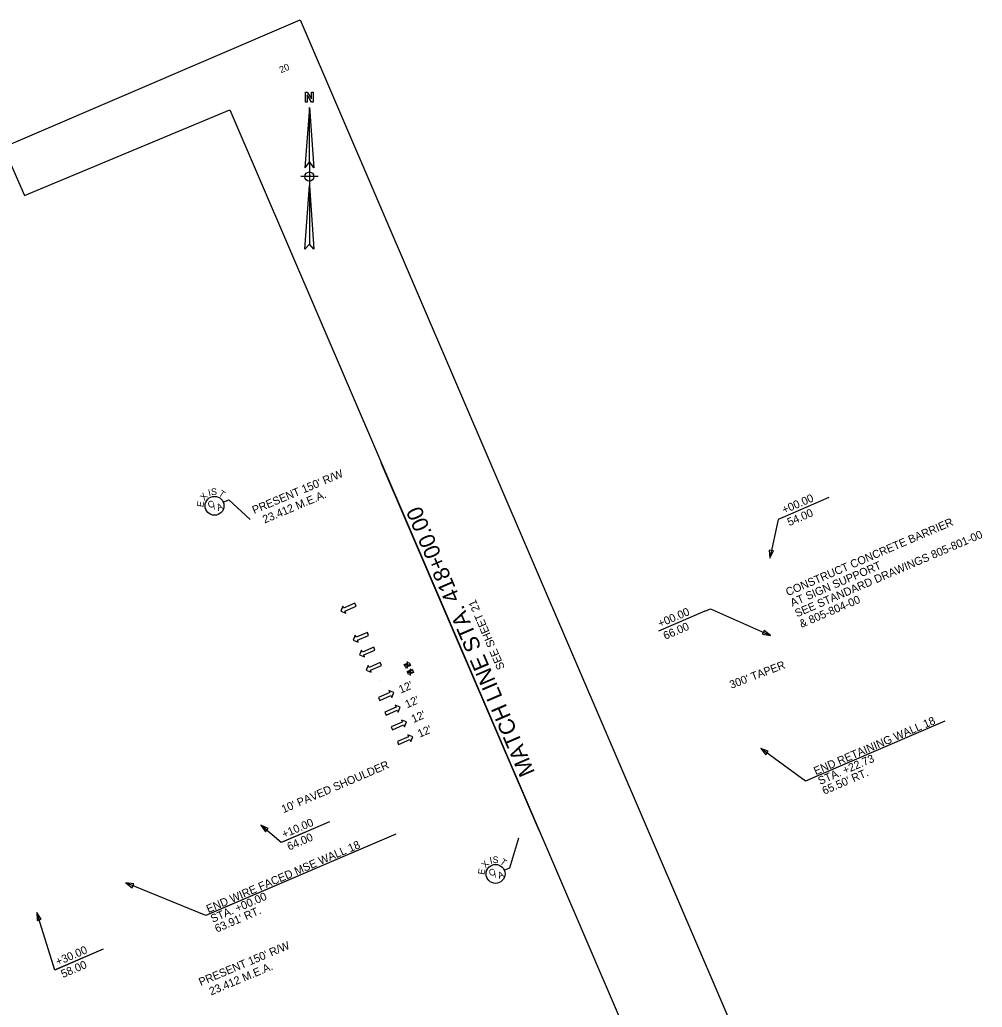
# Model space of a CAD drawing. Extents: x 1618233 to 1620283, y 1101130 to 1102832.
# Drawn here: x 1619562 to 1620283, y 1101953 to 1102693 of the extents above; entities that cross this region are included whole.
import ezdxf

# ---------------------------------------------------------------- set-up
doc = ezdxf.new("R2010")
doc.units = 0
for name, color, linetype in [('RD_EX_BldgApp', 7, 'Continuous'), ('RD_EX_Driveway', 7, 'Continuous'), ('RD_EX_Fence_Other', 7, 'Continuous'), ('RD_EX_H2O_WetLd', 7, 'Continuous'), ('RD_EX_Misc', 7, 'Continuous'), ('RD_EX_Misc_Golf_Teebox', 7, 'Continuous'), ('RD_EX_RailRoad', 7, 'Continuous'), ('RD_EX_UT', 7, 'Continuous'), ('RD_EX_VEG', 7, 'Continuous'), ('RD_HC_Data', 7, 'Continuous')]:
    doc.layers.add(name, color=color, linetype=linetype)

msp = doc.modelspace()

# ---------------------------------------------------------------- linework, layer by layer
at = {"layer": 'RD_EX_Driveway'}
for points in [[(1619854.18, 1102211.71), (1619855.07, 1102209.64), (1619851.38, 1102208.06), (1619850.49, 1102210.14), (1619854.18, 1102211.71)], [(1619855.28, 1102209.07), (1619855.15, 1102209.4), (1619851.45, 1102207.83), (1619851.58, 1102207.52)], [(1619856.34, 1102206.65), (1619856.4, 1102206.51), (1619852.83, 1102204.94), (1619852.76, 1102205.13)], [(1619856.54, 1102206.28), (1619857.42, 1102204.21), (1619853.73, 1102202.64), (1619852.85, 1102204.71), (1619856.54, 1102206.28)]]:
    msp.add_lwpolyline(points, dxfattribs=at)
at = {"layer": 'RD_EX_Fence_Other'}
msp.add_lwpolyline([(1618233.15, 1102032.67), (1619772.37, 1102693.29), (1620149.61, 1101814.32), (1618610.39, 1101153.71)], close=True, dxfattribs=at)
at = {"layer": 'RD_EX_H2O_WetLd'}
for p, q in [((1619852.82, 1102207.38), (1619852.82, 1102212.38)), ((1619850.32, 1102209.88), (1619855.32, 1102209.88)), ((1619852.63, 1102204.4), (1619857.63, 1102204.4)), ((1619855.13, 1102201.9), (1619855.13, 1102206.9))]:
    msp.add_line(p, q, dxfattribs=at)
at = {"layer": 'RD_EX_Misc'}
for points in [[(1619814.4, 1102253.86), (1619813.45, 1102256.07), (1619805.02, 1102252.45), (1619804.38, 1102253.94), (1619802.9, 1102250.23), (1619806.61, 1102248.75), (1619805.97, 1102250.24)], [(1619823.77, 1102232.01), (1619822.82, 1102234.22), (1619814.4, 1102230.6), (1619813.75, 1102232.1), (1619812.27, 1102228.38), (1619815.99, 1102226.9), (1619815.34, 1102228.4)], [(1619828.52, 1102220.96), (1619827.57, 1102223.16), (1619819.14, 1102219.54), (1619818.5, 1102221.04), (1619817.02, 1102217.33), (1619820.73, 1102215.84), (1619820.09, 1102217.34)], [(1619833.45, 1102209.45), (1619832.51, 1102211.66), (1619824.08, 1102208.04), (1619823.44, 1102209.54), (1619821.95, 1102205.82), (1619825.67, 1102204.34), (1619825.03, 1102205.84)], [(1619831.1, 1102185.52), (1619832.04, 1102183.32), (1619840.47, 1102186.94), (1619841.11, 1102185.44), (1619842.6, 1102189.15), (1619838.88, 1102190.64), (1619839.52, 1102189.14)], [(1619835.83, 1102174.5), (1619836.78, 1102172.29), (1619845.21, 1102175.91), (1619845.85, 1102174.41), (1619847.33, 1102178.13), (1619843.62, 1102179.61), (1619844.26, 1102178.11)], [(1619840.56, 1102163.47), (1619841.51, 1102161.26), (1619849.94, 1102164.88), (1619850.58, 1102163.39), (1619852.06, 1102167.1), (1619848.35, 1102168.58), (1619848.99, 1102167.09)], [(1619845.3, 1102152.44), (1619846.25, 1102150.24), (1619854.67, 1102153.86), (1619855.32, 1102152.36), (1619856.8, 1102156.07), (1619853.08, 1102157.56), (1619853.73, 1102156.06)]]:
    msp.add_lwpolyline(points, close=True, dxfattribs=at)
at = {"layer": 'RD_EX_Misc_Golf_Teebox'}
for p, q in [((1620168.57, 1102335.22), (1620133.9, 1102320.33)), ((1620075.65, 1102250.07), (1620040.97, 1102235.18)), ((1619832.91, 1102198.03), (1619832.91, 1102198.03)), ((1620255.38, 1102167.62), (1620159.08, 1102126.29)), ((1619794.32, 1102092.31), (1619758.89, 1102077.1)), ((1619844.14, 1102083.1), (1619704.08, 1102022.98)), ((1619624.92, 1101996.81), (1619589.48, 1101981.6))]:
    msp.add_line(p, q, dxfattribs=at)
for points in [[(1620133.9, 1102320.33), (1620130.41, 1102318.83), (1620124.18, 1102289.97)], [(1620075.65, 1102250.07), (1620079.95, 1102251.91), (1620124.66, 1102231.98)], [(1620159.08, 1102126.29), (1620151.05, 1102122.84), (1620117.5, 1102147.27)], [(1619794.32, 1102092.31), (1619758.14, 1102076.78), (1619743.01, 1102089.79)], [(1619844.14, 1102083.1), (1619701.89, 1102022.04), (1619641.89, 1102046.48)], [(1619624.92, 1101996.81), (1619588.65, 1101981.24), (1619575.24, 1102024.31)]]:
    msp.add_lwpolyline(points, dxfattribs=at)
for points in [[(1620123.89, 1102295.96), (1620124.18, 1102289.97), (1620126.92, 1102295.31)], [(1620118.73, 1102232.92), (1620124.66, 1102231.98), (1620120, 1102235.76)], [(1620123.1, 1102145.12), (1620117.5, 1102147.27), (1620121.27, 1102142.6)], [(1619748.42, 1102087.18), (1619743.01, 1102089.79), (1619746.39, 1102084.83)], [(1619647.85, 1102045.74), (1619641.89, 1102046.48), (1619646.68, 1102042.86)], [(1619578.44, 1102019.24), (1619575.24, 1102024.31), (1619575.48, 1102018.31)]]:
    msp.add_lwpolyline(points, close=True, dxfattribs=at)
at = {"layer": 'RD_EX_RailRoad'}
msp.add_lwpolyline([(1618327.62, 1102066.11), (1619552.64, 1102591.88), (1619565.97, 1102561.62), (1619719.68, 1102625.9), (1620077.33, 1101792.57), (1618698.92, 1101200.97)], close=True, dxfattribs=at)
msp.add_lwpolyline([(1618327.62, 1102066.11), (1619552.64, 1102591.88), (1619565.97, 1102561.62), (1619719.68, 1102625.9), (1620077.33, 1101792.57), (1618698.92, 1101200.97)], close=True, dxfattribs=at)
at = {"layer": 'RD_EX_UT'}
for p, q in [((1619779.34, 1102627.66), (1619775.92, 1102582.35)), ((1619779.34, 1102587), (1619775.92, 1102582.35)), ((1619779.34, 1102587), (1619779.34, 1102569.16)), ((1619785.86, 1102575.77), (1619772.89, 1102575.77)), ((1619779.34, 1102569.16), (1619782.76, 1102521.32)), ((1619782.76, 1102521.32), (1619779.34, 1102525.14))]:
    msp.add_line(p, q, dxfattribs=at)
msp.add_lwpolyline([(1619782.28, 1102631.49), (1619781.05, 1102631.49), (1619777.63, 1102636.95), (1619777.63, 1102636.13), (1619777.63, 1102631.49), (1619776.4, 1102631.49), (1619776.4, 1102639.07), (1619777.63, 1102639.07), (1619781.05, 1102634.02), (1619781.05, 1102634.43), (1619781.05, 1102639.07), (1619782.28, 1102639.07), (1619782.28, 1102631.49)], dxfattribs=at)
for points in [[(1619779.34, 1102627.66), (1619782.76, 1102582.35), (1619779.34, 1102587)], [(1619779.34, 1102569.16), (1619779.34, 1102525.14), (1619775.92, 1102521.32)]]:
    msp.add_lwpolyline(points, close=True, dxfattribs=at)
msp.add_circle((1619779.38, 1102575.77), 3.45, dxfattribs=at)
at = {"layer": 'RD_EX_VEG'}
msp.add_lwpolyline([(1619951.53, 1102085.69), (1619892.37, 1102223.53), (1619833.21, 1102361.38)], dxfattribs=at)
at = {"layer": 'RD_HC_Data'}
for p, q in [((1619714.82, 1102331.86), (1619719.02, 1102333.67)), ((1619719.02, 1102333.67), (1619735.11, 1102318.88)), ((1619929.57, 1102057.88), (1619936.23, 1102080.19)), ((1619925.36, 1102056.07), (1619929.57, 1102057.88))]:
    msp.add_line(p, q, dxfattribs=at)
for centre in [(1619708.31, 1102329.07), (1619918.85, 1102053.28)]:
    msp.add_circle(centre, 7.08, dxfattribs=at)

# ---------------------------------------------------------------- texts
at = {"layer": 'RD_EX_BldgApp'}
for s, p in [("PRESENT 150' R/W ", (1619738.04, 1102322.82)), ('  23.412 M.E.A.', (1619741.72, 1102314.06)), ("PRESENT 150' R/W ", (1619698.01, 1101969.2)), ('  23.412 M.E.A.', (1619701.69, 1101960.44))]:
    msp.add_text(s, height=6, rotation=22.77639, dxfattribs=at).set_placement(p)
at = {"layer": 'RD_EX_Misc_Golf_Teebox'}
for s, height, rotation, p in [('20', 5, 23.22835, (1619758.17, 1102653.18)), ('+00.00', 6, 23.22835, (1620134.95, 1102322.96)), ('54.00', 6, 23.22835, (1620138.89, 1102313.77)), ('CONSTRUCT CONCRETE BARRIER ', 6, 23.22835, (1620137.71, 1102261.34)), ('SEE STANDARD DRAWINGS 805-801-00', 6, 23.22835, (1620144.53, 1102245.45)), ('AT SIGN SUPPORT', 6, 23.22835, (1620141.12, 1102253.4)), ('& 805-804-00', 6, 23.22835, (1620147.94, 1102237.51)), ('+00.00', 6, 23.22835, (1620042.02, 1102237.81)), ('66.00', 6, 23.22835, (1620045.97, 1102228.62)), ("300' TAPER", 6, 20.93774, (1620095.4, 1102191.9)), ("12'", 6, 23.23465, (1619847.8, 1102188.34)), ("12'", 6, 23.23465, (1619852.53, 1102177.31)), ("12'", 6, 23.23465, (1619857.27, 1102166.28)), ('END RETAINING WALL 18', 6, 23.22998, (1620158.73, 1102127.23)), ("12'", 6, 23.23465, (1619862, 1102155.26)), ("10' PAVED SHOULDER", 6, 23.23628, (1619759.99, 1102098.68)), ('STA. +22.73', 6, 23.22998, (1620161.89, 1102119.88)), ("65.50' RT.", 6, 23.22998, (1620165.04, 1102112.53)), ('+10.00', 6, 23.22835, (1619760.32, 1102079.89)), ('64.00', 6, 23.22835, (1619764.26, 1102070.7)), ('END WIRE FACED MSE WALL 18', 6, 23.22998, (1619703.73, 1102023.92)), ('STA. +00.00', 6, 23.22998, (1619706.89, 1102016.57)), ("63.91' RT.", 6, 23.22998, (1619710.05, 1102009.22)), ('+30.00', 6, 23.22835, (1619590.91, 1101984.39)), ('58.00', 6, 23.22835, (1619594.85, 1101975.2))]:
    msp.add_text(s, height=height, rotation=rotation, dxfattribs=at).set_placement(p)
at = {"layer": 'RD_EX_VEG'}
for s, height, p in [('MATCH LINE STA. 418+00.00', 12, (1619948.54, 1102129.33)), ('SEE SHEET 21', 6, (1619925.93, 1102207.75))]:
    msp.add_text(s, height=height, rotation=113.22835, dxfattribs=at).set_placement(p)
at = {"layer": 'RD_HC_Data'}
for s, rotation, p in [('X', 48.32187, (1619700.7, 1102332.68)), ('I', 13.1604, (1619704.17, 1102336.4)), ('S', 1.43991, (1619705.74, 1102337.09)), ('T', 326.27843, (1619710.83, 1102337.1)), ('E', 81.80899, (1619699.97, 1102327.88)), ('C', 23.2251, (1619704.46, 1102326.99)), ('/', 23.2251, (1619708.01, 1102326.22)), ('A', 23.2251, (1619711, 1102325.17)), ('X', 46.36972, (1619911.37, 1102057.15)), ('I', 11.20824, (1619914.96, 1102060.75)), ('S', 359.48775, (1619916.56, 1102061.38)), ('T', 324.32628, (1619921.64, 1102061.22)), ('E', 79.85684, (1619910.48, 1102052.38)), ('C', 23.2251, (1619915, 1102051.2)), ('/', 23.2251, (1619918.55, 1102050.43)), ('A', 23.2251, (1619921.54, 1102049.38))]:
    msp.add_text(s, height=5, rotation=rotation, dxfattribs=at).set_placement(p)

doc.saveas('drawing.dxf')
